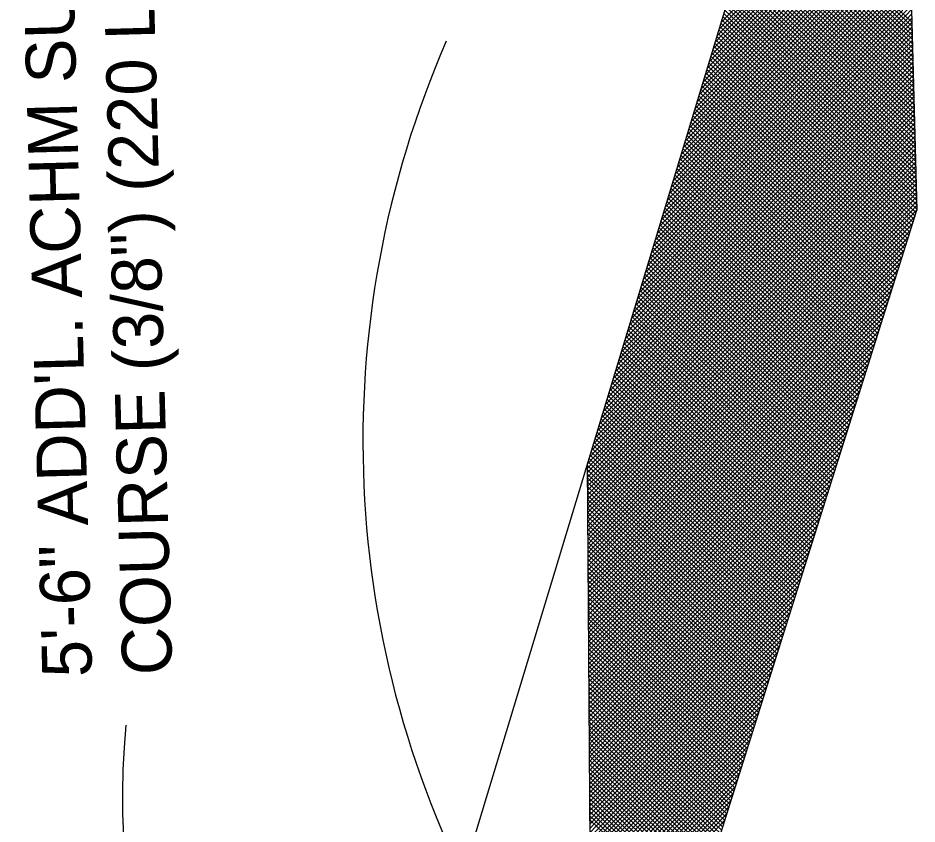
# Model space of a CAD drawing. Extents: x 1926836 to 1933254, y 596317 to 604524.
# Drawn here: x 1932978.1 to 1933087.6, y 600454.9 to 600553 of the extents above; entities that cross this region are included whole.
import ezdxf

# ---------------------------------------------------------------- set-up
doc = ezdxf.new("R2010")
doc.units = 0
doc.layers.add('Default', color=7, linetype='Continuous')

msp = doc.modelspace()

# ---------------------------------------------------------------- linework, layer by layer
at = {"layer": 'Default'}
for p, q in [((1933029.94, 600440.85), (1933085.12, 600623.02)), ((1933085.12, 600623.02), (1933087.62, 600529.6)), ((1933063.73, 600552.42), (1933086.37, 600576.31)), ((1933063.25, 600550.82), (1933086.4, 600575.25)), ((1933063.49, 600551.62), (1933086.38, 600575.78)), ((1933062.76, 600549.22), (1933086.43, 600574.19)), ((1933063.01, 600550.02), (1933086.41, 600574.72)), ((1933062.28, 600547.62), (1933086.46, 600573.13)), ((1933062.52, 600548.42), (1933086.44, 600573.66)), ((1933061.79, 600546.01), (1933086.48, 600572.07)), ((1933062.03, 600546.82), (1933086.47, 600572.6)), ((1933061.31, 600544.41), (1933086.51, 600571.01)), ((1933061.55, 600545.21), (1933086.5, 600571.54)), ((1933060.82, 600542.81), (1933086.54, 600569.95)), ((1933061.06, 600543.61), (1933086.53, 600570.48)), ((1933060.34, 600541.21), (1933086.57, 600568.89)), ((1933060.58, 600542.01), (1933086.56, 600569.42)), ((1933087.04, 600551.46), (1933068.7, 600568.83)), ((1933087.02, 600551.99), (1933068.82, 600569.23)), ((1933087.01, 600552.52), (1933068.95, 600569.64)), ((1933059.85, 600539.61), (1933086.6, 600567.83)), ((1933060.09, 600540.41), (1933086.58, 600568.36)), ((1933087.08, 600549.87), (1933068.34, 600567.63)), ((1933087.07, 600550.4), (1933068.46, 600568.03)), ((1933087.05, 600550.93), (1933068.58, 600568.43)), ((1933059.37, 600538), (1933086.63, 600566.77)), ((1933059.61, 600538.8), (1933086.61, 600567.3)), ((1933087.11, 600548.81), (1933068.1, 600566.83)), ((1933087.09, 600549.34), (1933068.22, 600567.23)), ((1933058.88, 600536.4), (1933086.66, 600565.71)), ((1933059.12, 600537.2), (1933086.64, 600566.24)), ((1933087.15, 600547.22), (1933067.73, 600565.62)), ((1933087.14, 600547.75), (1933067.85, 600566.02)), ((1933087.12, 600548.28), (1933067.97, 600566.42)), ((1933058.39, 600534.8), (1933086.68, 600564.65)), ((1933058.64, 600535.6), (1933086.67, 600565.18)), ((1933087.19, 600545.63), (1933067.37, 600564.42)), ((1933087.18, 600546.16), (1933067.49, 600564.82)), ((1933087.17, 600546.69), (1933067.61, 600565.22)), ((1933057.91, 600533.2), (1933086.71, 600563.59)), ((1933058.15, 600534), (1933086.7, 600564.12)), ((1933087.24, 600544.04), (1933067, 600563.21)), ((1933087.22, 600544.57), (1933067.12, 600563.61)), ((1933087.21, 600545.1), (1933067.24, 600564.02)), ((1933057.42, 600531.59), (1933086.74, 600562.53)), ((1933057.67, 600532.39), (1933086.73, 600563.06)), ((1933087.27, 600542.98), (1933066.76, 600562.41)), ((1933087.25, 600543.51), (1933066.88, 600562.81)), ((1933056.94, 600529.99), (1933086.77, 600561.47)), ((1933057.18, 600530.79), (1933086.75, 600562)), ((1933087.31, 600541.38), (1933066.39, 600561.21)), ((1933087.29, 600541.92), (1933066.51, 600561.61)), ((1933087.28, 600542.45), (1933066.64, 600562.01)), ((1933056.21, 600527.59), (1933086.81, 600559.88)), ((1933056.45, 600528.39), (1933086.8, 600560.41)), ((1933056.7, 600529.19), (1933086.78, 600560.94)), ((1933087.35, 600539.79), (1933066.03, 600560)), ((1933087.34, 600540.32), (1933066.15, 600560.4)), ((1933087.32, 600540.85), (1933066.27, 600560.8)), ((1933055.72, 600525.98), (1933086.84, 600558.82)), ((1933055.97, 600526.79), (1933086.83, 600559.35)), ((1933087.39, 600538.2), (1933065.66, 600558.8)), ((1933087.38, 600538.73), (1933065.79, 600559.2)), ((1933087.36, 600539.26), (1933065.91, 600559.6)), ((1933055.24, 600524.38), (1933086.87, 600557.76)), ((1933055.48, 600525.18), (1933086.85, 600558.29)), ((1933087.42, 600537.14), (1933065.42, 600557.99)), ((1933087.41, 600537.67), (1933065.54, 600558.4)), ((1933054.75, 600522.78), (1933086.9, 600556.7)), ((1933055, 600523.58), (1933086.88, 600557.23)), ((1933087.46, 600535.55), (1933065.06, 600556.79)), ((1933087.45, 600536.08), (1933065.18, 600557.19)), ((1933087.44, 600536.61), (1933065.3, 600557.59)), ((1933054.27, 600521.18), (1933086.93, 600555.64)), ((1933054.51, 600521.98), (1933086.91, 600556.17)), ((1933087.51, 600533.96), (1933064.69, 600555.59)), ((1933087.49, 600534.49), (1933064.81, 600555.99)), ((1933087.48, 600535.02), (1933064.93, 600556.39)), ((1933053.78, 600519.57), (1933086.95, 600554.58)), ((1933054.03, 600520.38), (1933086.94, 600555.11)), ((1933087.54, 600532.9), (1933064.45, 600554.78)), ((1933087.52, 600533.43), (1933064.57, 600555.19)), ((1933053.3, 600517.97), (1933086.98, 600553.51)), ((1933053.54, 600518.77), (1933086.97, 600554.04)), ((1933087.58, 600531.31), (1933064.08, 600553.58)), ((1933087.56, 600531.84), (1933064.2, 600553.98)), ((1933087.55, 600532.37), (1933064.33, 600554.38)), ((1933052.81, 600516.37), (1933087.01, 600552.45)), ((1933053.06, 600517.17), (1933087, 600552.98)), ((1933087.62, 600529.72), (1933063.72, 600552.38)), ((1933087.61, 600530.25), (1933063.84, 600552.78)), ((1933087.59, 600530.78), (1933063.96, 600553.18)), ((1933052.33, 600514.77), (1933087.04, 600551.39)), ((1933052.57, 600515.57), (1933087.03, 600551.92)), ((1933087.28, 600528.5), (1933063.35, 600551.17)), ((1933087.4, 600528.9), (1933063.48, 600551.57)), ((1933087.53, 600529.29), (1933063.6, 600551.97)), ((1933051.84, 600513.16), (1933087.07, 600550.33)), ((1933052.08, 600513.97), (1933087.05, 600550.86)), ((1933087.03, 600527.7), (1933063.11, 600550.37)), ((1933087.15, 600528.1), (1933063.23, 600550.77)), ((1933051.36, 600511.56), (1933087.1, 600549.27)), ((1933051.6, 600512.36), (1933087.08, 600549.8)), ((1933086.65, 600526.51), (1933062.75, 600549.16)), ((1933086.78, 600526.91), (1933062.87, 600549.57)), ((1933086.9, 600527.3), (1933062.99, 600549.97)), ((1933050.87, 600509.96), (1933087.12, 600548.21)), ((1933051.11, 600510.76), (1933087.11, 600548.74)), ((1933086.27, 600525.32), (1933062.38, 600547.96)), ((1933086.4, 600525.71), (1933062.5, 600548.36)), ((1933086.52, 600526.11), (1933062.62, 600548.76)), ((1933050.39, 600508.36), (1933087.15, 600547.15)), ((1933050.63, 600509.16), (1933087.14, 600547.68)), ((1933085.9, 600524.12), (1933062.02, 600546.76)), ((1933086.02, 600524.52), (1933062.14, 600547.16)), ((1933086.15, 600524.92), (1933062.26, 600547.56)), ((1933049.9, 600506.76), (1933087.18, 600546.09)), ((1933050.14, 600507.56), (1933087.17, 600546.62)), ((1933085.65, 600523.33), (1933061.77, 600545.95)), ((1933085.77, 600523.72), (1933061.89, 600546.35)), ((1933049.42, 600505.15), (1933087.21, 600545.03)), ((1933049.66, 600505.95), (1933087.2, 600545.56)), ((1933085.27, 600522.13), (1933061.41, 600544.75)), ((1933085.4, 600522.53), (1933061.53, 600545.15)), ((1933085.52, 600522.93), (1933061.65, 600545.55)), ((1933048.93, 600503.55), (1933087.24, 600543.97)), ((1933049.17, 600504.35), (1933087.22, 600544.5)), ((1933084.89, 600520.94), (1933061.04, 600543.54)), ((1933085.02, 600521.34), (1933061.16, 600543.95)), ((1933085.14, 600521.74), (1933061.29, 600544.35)), ((1933048.2, 600501.15), (1933087.28, 600542.38)), ((1933048.44, 600501.95), (1933087.27, 600542.91)), ((1933048.69, 600502.75), (1933087.25, 600543.44)), ((1933084.64, 600520.15), (1933060.8, 600542.74)), ((1933084.77, 600520.54), (1933060.92, 600543.14)), ((1933047.72, 600499.54), (1933087.31, 600541.32)), ((1933047.96, 600500.35), (1933087.3, 600541.85)), ((1933084.27, 600518.95), (1933060.44, 600541.54)), ((1933084.39, 600519.35), (1933060.56, 600541.94)), ((1933084.52, 600519.75), (1933060.68, 600542.34)), ((1933047.48, 600498.75), (1933087.32, 600540.79)), ((1933047.49, 600498.21), (1933087.34, 600540.26)), ((1933083.89, 600517.76), (1933060.07, 600540.33)), ((1933084.02, 600518.16), (1933060.19, 600540.73)), ((1933084.14, 600518.55), (1933060.31, 600541.14)), ((1933047.49, 600497.67), (1933087.35, 600539.73)), ((1933047.5, 600497.13), (1933087.37, 600539.2)), ((1933083.51, 600516.57), (1933059.71, 600539.13)), ((1933083.64, 600516.96), (1933059.83, 600539.53)), ((1933083.76, 600517.36), (1933059.95, 600539.93)), ((1933047.5, 600496.59), (1933087.38, 600538.67)), ((1933047.5, 600496.05), (1933087.4, 600538.14)), ((1933083.26, 600515.77), (1933059.46, 600538.33)), ((1933083.39, 600516.17), (1933059.58, 600538.73)), ((1933047.51, 600495.51), (1933087.41, 600537.61)), ((1933047.51, 600494.97), (1933087.42, 600537.08)), ((1933082.89, 600514.58), (1933059.1, 600537.12)), ((1933083.01, 600514.97), (1933059.22, 600537.52)), ((1933083.14, 600515.37), (1933059.34, 600537.92)), ((1933047.51, 600494.42), (1933087.44, 600536.55)), ((1933047.52, 600493.88), (1933087.45, 600536.02)), ((1933082.51, 600513.38), (1933058.73, 600535.92)), ((1933082.63, 600513.78), (1933058.85, 600536.32)), ((1933082.76, 600514.18), (1933058.98, 600536.72)), ((1933047.52, 600493.34), (1933087.47, 600535.49)), ((1933047.53, 600492.8), (1933087.48, 600534.96)), ((1933082.13, 600512.19), (1933058.37, 600534.71)), ((1933082.26, 600512.59), (1933058.49, 600535.11)), ((1933082.38, 600512.99), (1933058.61, 600535.52)), ((1933047.53, 600492.26), (1933087.49, 600534.43)), ((1933047.53, 600491.72), (1933087.51, 600533.9)), ((1933081.88, 600511.4), (1933058.13, 600533.91)), ((1933082.01, 600511.79), (1933058.25, 600534.31)), ((1933047.54, 600491.18), (1933087.52, 600533.37)), ((1933047.54, 600490.64), (1933087.54, 600532.84)), ((1933081.51, 600510.2), (1933057.76, 600532.71)), ((1933081.63, 600510.6), (1933057.88, 600533.11)), ((1933081.76, 600511), (1933058, 600533.51)), ((1933047.54, 600490.1), (1933087.55, 600532.31)), ((1933047.55, 600489.55), (1933087.57, 600531.78)), ((1933081.13, 600509.01), (1933057.4, 600531.5)), ((1933081.25, 600509.41), (1933057.52, 600531.9)), ((1933081.38, 600509.8), (1933057.64, 600532.3)), ((1933047.55, 600489.01), (1933087.58, 600531.25)), ((1933047.56, 600488.47), (1933087.59, 600530.72)), ((1933080.88, 600508.21), (1933057.15, 600530.7)), ((1933081, 600508.61), (1933057.27, 600531.1)), ((1933028.65, 600342.66), (1933087.62, 600529.6)), ((1933047.56, 600487.93), (1933087.61, 600530.19)), ((1933047.56, 600487.39), (1933087.62, 600529.66)), ((1933080.5, 600507.02), (1933056.79, 600529.49)), ((1933080.63, 600507.42), (1933056.91, 600529.9)), ((1933080.75, 600507.82), (1933057.03, 600530.3)), ((1933047.57, 600486.85), (1933087.4, 600528.87)), ((1933080.13, 600505.83), (1933056.42, 600528.29)), ((1933080.25, 600506.22), (1933056.54, 600528.69)), ((1933080.38, 600506.62), (1933056.67, 600529.09)), ((1933047.57, 600486.31), (1933087.14, 600528.06)), ((1933047.57, 600485.77), (1933086.88, 600527.24)), ((1933079.75, 600504.63), (1933056.06, 600527.09)), ((1933079.87, 600505.03), (1933056.18, 600527.49)), ((1933080, 600505.43), (1933056.3, 600527.89)), ((1933047.58, 600485.22), (1933086.62, 600526.42)), ((1933079.5, 600503.84), (1933055.82, 600526.28)), ((1933079.62, 600504.24), (1933055.94, 600526.68)), ((1933047.58, 600484.68), (1933086.36, 600525.61)), ((1933079.12, 600502.64), (1933055.45, 600525.08)), ((1933079.25, 600503.04), (1933055.57, 600525.48)), ((1933079.37, 600503.44), (1933055.69, 600525.88)), ((1933047.59, 600484.14), (1933086.11, 600524.79)), ((1933047.59, 600483.6), (1933085.85, 600523.97)), ((1933078.74, 600501.45), (1933055.09, 600523.87)), ((1933078.87, 600501.85), (1933055.21, 600524.28)), ((1933079, 600502.25), (1933055.33, 600524.68)), ((1933047.59, 600483.06), (1933085.59, 600523.15)), ((1933078.37, 600500.26), (1933054.72, 600522.67)), ((1933078.49, 600500.66), (1933054.84, 600523.07)), ((1933078.62, 600501.05), (1933054.96, 600523.47)), ((1933047.6, 600482.52), (1933085.33, 600522.34)), ((1933078.12, 600499.46), (1933054.48, 600521.87)), ((1933078.24, 600499.86), (1933054.6, 600522.27)), ((1933047.6, 600481.98), (1933085.08, 600521.52)), ((1933047.6, 600481.44), (1933084.82, 600520.7)), ((1933077.74, 600498.27), (1933054.11, 600520.66)), ((1933077.87, 600498.67), (1933054.23, 600521.06)), ((1933077.99, 600499.07), (1933054.36, 600521.47)), ((1933047.61, 600480.89), (1933084.56, 600519.89)), ((1933077.36, 600497.08), (1933053.75, 600519.46)), ((1933077.49, 600497.47), (1933053.87, 600519.86)), ((1933077.62, 600497.87), (1933053.99, 600520.26)), ((1933047.61, 600480.35), (1933084.3, 600519.07)), ((1933047.62, 600479.81), (1933084.04, 600518.25)), ((1933076.99, 600495.88), (1933053.38, 600518.25)), ((1933077.11, 600496.28), (1933053.51, 600518.66)), ((1933077.24, 600496.68), (1933053.63, 600519.06)), ((1933047.62, 600479.27), (1933083.79, 600517.43)), ((1933076.74, 600495.09), (1933053.14, 600517.45)), ((1933076.86, 600495.49), (1933053.26, 600517.85)), ((1933047.62, 600478.73), (1933083.53, 600516.62)), ((1933076.36, 600493.89), (1933052.78, 600516.25)), ((1933076.49, 600494.29), (1933052.9, 600516.65)), ((1933076.61, 600494.69), (1933053.02, 600517.05)), ((1933047.63, 600478.19), (1933083.27, 600515.8)), ((1933047.63, 600477.65), (1933083.01, 600514.98)), ((1933075.98, 600492.7), (1933052.41, 600515.04)), ((1933076.11, 600493.1), (1933052.53, 600515.44)), ((1933076.24, 600493.5), (1933052.65, 600515.85)), ((1933047.64, 600477.11), (1933082.76, 600514.16)), ((1933075.73, 600491.91), (1933052.17, 600514.24)), ((1933075.86, 600492.3), (1933052.29, 600514.64)), ((1933047.64, 600476.57), (1933082.5, 600513.35)), ((1933075.36, 600490.71), (1933051.8, 600513.04)), ((1933075.48, 600491.11), (1933051.92, 600513.44)), ((1933075.61, 600491.51), (1933052.05, 600513.84)), ((1933047.64, 600476.02), (1933082.24, 600512.53)), ((1933047.65, 600475.48), (1933081.98, 600511.71)), ((1933074.98, 600489.52), (1933051.44, 600511.83)), ((1933075.11, 600489.92), (1933051.56, 600512.23)), ((1933075.23, 600490.32), (1933051.68, 600512.63)), ((1933047.65, 600474.94), (1933081.72, 600510.9)), ((1933074.6, 600488.33), (1933051.07, 600510.63)), ((1933074.73, 600488.72), (1933051.2, 600511.03)), ((1933074.86, 600489.12), (1933051.32, 600511.43)), ((1933047.65, 600474.4), (1933081.47, 600510.08)), ((1933074.35, 600487.53), (1933050.83, 600509.82)), ((1933074.48, 600487.93), (1933050.95, 600510.23)), ((1933047.66, 600473.86), (1933081.21, 600509.26)), ((1933047.66, 600473.32), (1933080.95, 600508.44)), ((1933073.98, 600486.34), (1933050.47, 600508.62)), ((1933074.1, 600486.74), (1933050.59, 600509.02)), ((1933074.23, 600487.13), (1933050.71, 600509.42)), ((1933047.67, 600472.78), (1933080.69, 600507.63)), ((1933073.6, 600485.14), (1933050.1, 600507.42)), ((1933073.73, 600485.54), (1933050.22, 600507.82)), ((1933073.85, 600485.94), (1933050.34, 600508.22)), ((1933047.67, 600472.24), (1933080.44, 600506.81)), ((1933073.22, 600483.95), (1933049.74, 600506.21)), ((1933073.35, 600484.35), (1933049.86, 600506.61)), ((1933073.47, 600484.75), (1933049.98, 600507.01)), ((1933047.67, 600471.69), (1933080.18, 600505.99)), ((1933047.68, 600471.15), (1933079.92, 600505.18)), ((1933072.97, 600483.16), (1933049.49, 600505.41)), ((1933073.1, 600483.55), (1933049.61, 600505.81)), ((1933047.68, 600470.61), (1933079.66, 600504.36)), ((1933072.6, 600481.96), (1933049.13, 600504.2)), ((1933072.72, 600482.36), (1933049.25, 600504.61)), ((1933072.85, 600482.76), (1933049.37, 600505.01)), ((1933047.68, 600470.07), (1933079.4, 600503.54)), ((1933072.22, 600480.77), (1933048.76, 600503)), ((1933072.35, 600481.17), (1933048.88, 600503.4)), ((1933072.47, 600481.56), (1933049.01, 600503.8)), ((1933047.69, 600469.53), (1933079.15, 600502.72)), ((1933047.69, 600468.99), (1933078.89, 600501.91)), ((1933071.97, 600479.97), (1933048.52, 600502.2)), ((1933072.09, 600480.37), (1933048.64, 600502.6)), ((1933047.7, 600468.45), (1933078.63, 600501.09)), ((1933071.59, 600478.78), (1933048.16, 600500.99)), ((1933071.72, 600479.18), (1933048.28, 600501.39)), ((1933071.84, 600479.58), (1933048.4, 600501.8)), ((1933047.7, 600467.91), (1933078.37, 600500.27)), ((1933071.22, 600477.59), (1933047.79, 600499.79)), ((1933071.34, 600477.99), (1933047.91, 600500.19)), ((1933071.47, 600478.38), (1933048.03, 600500.59)), ((1933050.22, 600105.35), (1933047.48, 600498.79)), ((1933070.97, 600476.79), (1933047.55, 600498.99)), ((1933071.09, 600477.19), (1933047.67, 600499.39)), ((1933047.7, 600467.37), (1933078.12, 600499.46)), ((1933047.71, 600466.82), (1933077.86, 600498.64)), ((1933070.84, 600476.39), (1933047.49, 600498.53)), ((1933070.71, 600476), (1933047.49, 600498.01)), ((1933070.59, 600475.6), (1933047.49, 600497.49)), ((1933047.71, 600466.28), (1933077.6, 600497.82)), ((1933070.46, 600475.2), (1933047.5, 600496.97)), ((1933070.34, 600474.8), (1933047.5, 600496.45)), ((1933047.71, 600465.74), (1933077.34, 600497)), ((1933070.21, 600474.41), (1933047.5, 600495.93)), ((1933070.09, 600474.01), (1933047.51, 600495.41)), ((1933047.72, 600465.2), (1933077.08, 600496.19)), ((1933047.72, 600464.66), (1933076.83, 600495.37)), ((1933069.96, 600473.61), (1933047.51, 600494.89)), ((1933069.84, 600473.21), (1933047.52, 600494.37)), ((1933047.73, 600464.12), (1933076.57, 600494.55)), ((1933069.71, 600472.81), (1933047.52, 600493.85)), ((1933069.59, 600472.42), (1933047.52, 600493.33)), ((1933047.73, 600463.58), (1933076.31, 600493.74)), ((1933069.46, 600472.02), (1933047.53, 600492.81)), ((1933069.33, 600471.62), (1933047.53, 600492.29)), ((1933047.73, 600463.04), (1933076.05, 600492.92)), ((1933047.74, 600462.49), (1933075.8, 600492.1)), ((1933069.21, 600471.22), (1933047.53, 600491.77)), ((1933069.08, 600470.83), (1933047.54, 600491.25)), ((1933047.74, 600461.95), (1933075.54, 600491.28)), ((1933068.96, 600470.43), (1933047.54, 600490.73)), ((1933068.83, 600470.03), (1933047.54, 600490.21)), ((1933047.74, 600461.41), (1933075.28, 600490.47)), ((1933068.71, 600469.63), (1933047.55, 600489.69)), ((1933068.58, 600469.24), (1933047.55, 600489.17)), ((1933047.75, 600460.87), (1933075.02, 600489.65)), ((1933047.75, 600460.33), (1933074.76, 600488.83)), ((1933068.46, 600468.84), (1933047.55, 600488.65)), ((1933068.33, 600468.44), (1933047.56, 600488.13)), ((1933068.2, 600468.04), (1933047.56, 600487.61)), ((1933047.76, 600459.79), (1933074.51, 600488.02)), ((1933068.08, 600467.64), (1933047.57, 600487.09)), ((1933067.95, 600467.25), (1933047.57, 600486.57)), ((1933047.76, 600459.25), (1933074.25, 600487.2)), ((1933067.83, 600466.85), (1933047.57, 600486.05)), ((1933067.7, 600466.45), (1933047.58, 600485.53)), ((1933047.76, 600458.71), (1933073.99, 600486.38)), ((1933047.77, 600458.17), (1933073.73, 600485.56)), ((1933067.58, 600466.05), (1933047.58, 600485.01)), ((1933067.45, 600465.66), (1933047.58, 600484.48)), ((1933047.77, 600457.62), (1933073.47, 600484.75)), ((1933067.33, 600465.26), (1933047.59, 600483.96)), ((1933067.2, 600464.86), (1933047.59, 600483.44)), ((1933047.77, 600457.08), (1933073.22, 600483.93)), ((1933067.08, 600464.46), (1933047.59, 600482.92)), ((1933066.95, 600464.06), (1933047.6, 600482.4)), ((1933047.78, 600456.54), (1933072.96, 600483.11)), ((1933047.78, 600456), (1933072.7, 600482.29)), ((1933066.82, 600463.67), (1933047.6, 600481.88)), ((1933066.7, 600463.27), (1933047.61, 600481.36)), ((1933047.79, 600455.46), (1933072.44, 600481.48)), ((1933066.57, 600462.87), (1933047.61, 600480.84)), ((1933066.45, 600462.47), (1933047.61, 600480.32)), ((1933047.79, 600454.92), (1933072.19, 600480.66)), ((1933066.32, 600462.08), (1933047.62, 600479.8)), ((1933066.2, 600461.68), (1933047.62, 600479.28)), ((1933047.79, 600454.38), (1933071.93, 600479.84)), ((1933047.8, 600453.84), (1933071.67, 600479.03)), ((1933066.07, 600461.28), (1933047.62, 600478.76)), ((1933065.95, 600460.88), (1933047.63, 600478.24)), ((1933065.82, 600460.48), (1933047.63, 600477.72)), ((1933047.8, 600453.29), (1933071.41, 600478.21)), ((1933065.7, 600460.09), (1933047.63, 600477.2)), ((1933065.57, 600459.69), (1933047.64, 600476.68)), ((1933047.8, 600452.75), (1933071.15, 600477.39)), ((1933065.44, 600459.29), (1933047.64, 600476.16)), ((1933065.32, 600458.89), (1933047.65, 600475.64)), ((1933047.81, 600452.21), (1933070.9, 600476.57)), ((1933047.81, 600451.67), (1933070.64, 600475.76)), ((1933065.19, 600458.5), (1933047.65, 600475.12)), ((1933065.07, 600458.1), (1933047.65, 600474.6)), ((1933047.82, 600451.13), (1933070.38, 600474.94)), ((1933064.94, 600457.7), (1933047.66, 600474.08)), ((1933064.82, 600457.3), (1933047.66, 600473.56)), ((1933047.82, 600450.59), (1933070.12, 600474.12)), ((1933064.69, 600456.91), (1933047.66, 600473.04)), ((1933064.57, 600456.51), (1933047.67, 600472.52)), ((1933047.82, 600450.05), (1933069.87, 600473.31)), ((1933047.83, 600449.51), (1933069.61, 600472.49)), ((1933064.44, 600456.11), (1933047.67, 600472)), ((1933064.32, 600455.71), (1933047.67, 600471.48)), ((1933047.83, 600448.97), (1933069.35, 600471.67)), ((1933064.19, 600455.31), (1933047.68, 600470.96)), ((1933064.06, 600454.92), (1933047.68, 600470.44)), ((1933047.83, 600448.42), (1933069.09, 600470.85)), ((1933063.94, 600454.52), (1933047.68, 600469.92)), ((1933063.81, 600454.12), (1933047.69, 600469.4)), ((1933047.84, 600447.88), (1933068.83, 600470.04)), ((1933047.84, 600447.34), (1933068.58, 600469.22)), ((1933063.69, 600453.72), (1933047.69, 600468.88)), ((1933063.56, 600453.33), (1933047.7, 600468.36)), ((1933047.85, 600446.8), (1933068.32, 600468.4)), ((1933063.44, 600452.93), (1933047.7, 600467.84)), ((1933063.31, 600452.53), (1933047.7, 600467.32)), ((1933063.19, 600452.13), (1933047.71, 600466.8)), ((1933047.85, 600446.26), (1933068.06, 600467.59)), ((1933063.06, 600451.73), (1933047.71, 600466.28)), ((1933062.93, 600451.34), (1933047.71, 600465.76)), ((1933047.85, 600445.72), (1933067.8, 600466.77)), ((1933047.86, 600445.18), (1933067.55, 600465.95)), ((1933062.81, 600450.94), (1933047.72, 600465.24)), ((1933062.68, 600450.54), (1933047.72, 600464.72)), ((1933047.86, 600444.64), (1933067.29, 600465.13)), ((1933062.56, 600450.14), (1933047.72, 600464.2)), ((1933062.43, 600449.75), (1933047.73, 600463.68)), ((1933047.86, 600444.09), (1933067.03, 600464.32)), ((1933047.87, 600443.55), (1933066.77, 600463.5)), ((1933062.31, 600449.35), (1933047.73, 600463.16)), ((1933062.18, 600448.95), (1933047.74, 600462.64)), ((1933047.87, 600443.01), (1933066.51, 600462.68)), ((1933062.06, 600448.55), (1933047.74, 600462.12)), ((1933061.93, 600448.16), (1933047.74, 600461.6)), ((1933047.88, 600442.47), (1933066.26, 600461.87)), ((1933061.81, 600447.76), (1933047.75, 600461.08)), ((1933061.68, 600447.36), (1933047.75, 600460.56)), ((1933047.88, 600441.93), (1933066, 600461.05)), ((1933047.88, 600441.39), (1933065.74, 600460.23)), ((1933061.55, 600446.96), (1933047.75, 600460.04)), ((1933061.43, 600446.56), (1933047.76, 600459.52)), ((1933047.89, 600440.85), (1933065.48, 600459.41)), ((1933061.3, 600446.17), (1933047.76, 600459)), ((1933061.18, 600445.77), (1933047.76, 600458.48)), ((1933047.89, 600440.31), (1933065.23, 600458.6)), ((1933061.05, 600445.37), (1933047.77, 600457.96)), ((1933060.93, 600444.97), (1933047.77, 600457.44)), ((1933060.8, 600444.58), (1933047.78, 600456.92)), ((1933047.89, 600439.76), (1933064.97, 600457.78)), ((1933047.9, 600439.22), (1933064.71, 600456.96)), ((1933060.68, 600444.18), (1933047.78, 600456.4)), ((1933060.55, 600443.78), (1933047.78, 600455.88)), ((1933047.9, 600438.68), (1933064.45, 600456.15)), ((1933060.43, 600443.38), (1933047.79, 600455.36)), ((1933047.91, 600438.14), (1933064.19, 600455.33))]:
    msp.add_line(p, q, dxfattribs=at)
msp.add_arc((1933141.83, 600501.5), 121.72, 156.4253, 208.6755, dxfattribs=at)
msp.add_ellipse((1933031.22, 600463.11), major_axis=(-5.79, -60.98), ratio=0.655798, start_param=4.712389, end_param=6.093533, dxfattribs=at)

# ---------------------------------------------------------------- texts
for s, p in [('COURSE (3/8") (220 LBS. PER SQ. YD.)', (1932996.89, 600473.08)), ('5\'-6" ADD\'L. ACHM SURFACE ', (1932987.13, 600472.82))]:
    msp.add_text(s, height=6.075, rotation=91.5377, dxfattribs=at).set_placement(p)

doc.saveas('drawing.dxf')
